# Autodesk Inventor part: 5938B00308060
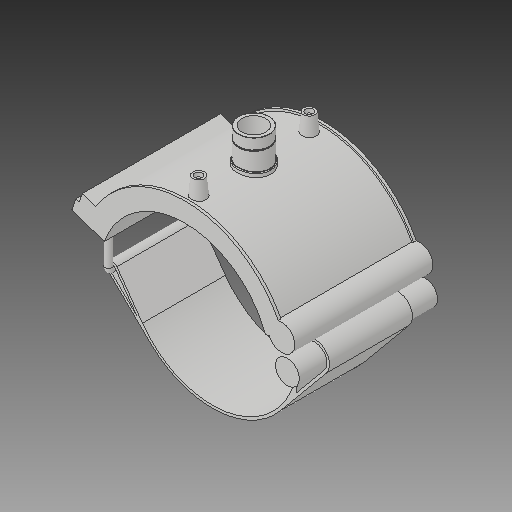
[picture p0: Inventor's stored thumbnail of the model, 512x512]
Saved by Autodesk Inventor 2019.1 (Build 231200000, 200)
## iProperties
Created: 2017-07
Part Number: 5938B00308060
Material: Generic
Description: PLASSON TRANSITION SADDLE 8''IPS x 1"NPT
Document SubType Name: Modeling
Designer: KIM
Density: 1 g/cm^3
Appearance: Default
Author: KIM
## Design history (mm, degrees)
derived "5938B.ipt"
feature "Solid1::5938B.ipt"
tag "TaggingFeature1"
body "Solid1"
other parameters: "d0" = 218.7, "d1" = 262.44, "d2" = 449.58, "d3" = 54.675, "d4" = 176.022, "d5" = 0, "d40" = 136.4688, "d41" = 42.4074, "d43" = 0, "d45" = 0, "d47" = 173.13, "d48" = 39.3783, "d50" = 0, "d78" = 153.22, "d79" = 15, "d80" = 70.4088, "d82" = 5 deg, "d84" = 4, "d85" = 14, "d86" = 0, "d87" = 3, "d88" = 0, "d96" = 267.6888, "d97" = 3.52044, "d98" = 0, "d102" = 0.90873, "d103" = 30.291, "d104" = 25.146, "d105" = 0, "d106" = 24.2328, "d108" = 0, "d109" = -13.97, "d111" = 0.5, "d112" = 0.5, "d113" = 0, "d114" = 0.5, "d117" = 0.30291, "d120" = 140 deg, "d121" = 24.228, "d122" = 20 deg, "d123" = 1049.76, "d124" = 157.464, "d126" = 0, "d143" = 225.261, "d145" = 33.64615, "d149" = 3.2805, "d150" = 37.01077, "d153" = 176.022, "d154" = 0, "d156" = 131.22, "d157" = 160 deg, "d159" = 8.748, "d161" = 3.2805, "d162" = 105.6132, "d163" = 0, "d164" = 109.35, "d167" = 21.87, "d168" = 128.01951, "d170" = 3.2805, "d172" = 0, "d173" = 1, "d175" = 109.35, "d176" = 20 deg, "d177" = 15.309, "d178" = 43.74, "d180" = 0, "d183" = 17.496, "d184" = 12.2472, "d185" = 57.20715, "d186" = 57.20715, "d187" = 131.22, "d188" = 13.122, "d189" = 15.309, "d190" = 0, "d191" = 157.464, "d193" = 8.748, "d194" = 4.48335, "d195" = 90 deg, "d197" = 0, "d199" = 0, "d_" = 218.7, "B_" = 179.832, "H_" = 41.91, "L_" = 176.022, "d_t" = 6, "G_" = 30.291, "d148" = 3.2805, "d160" = 3.2805, "d169" = 3.2805, "d192" = 8.748
